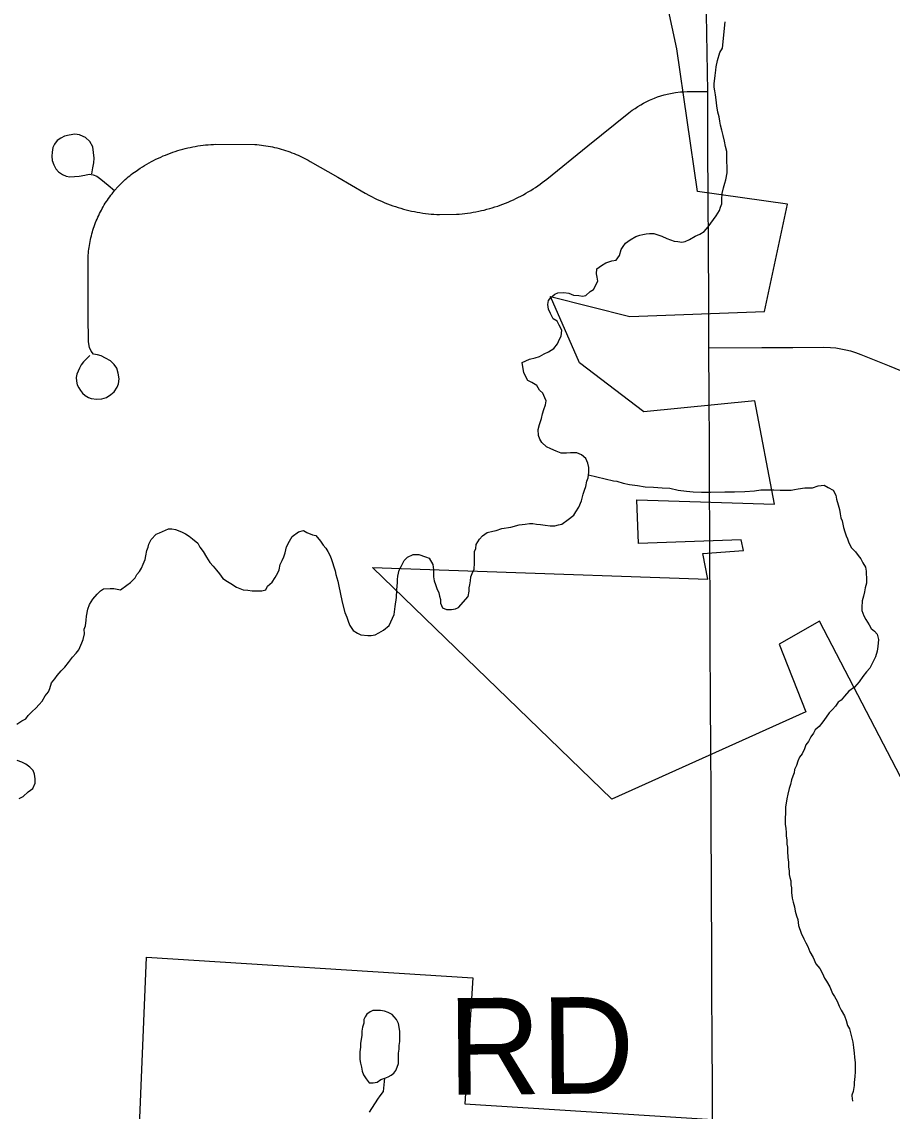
# Model space of a CAD drawing. Extents: x -11.4 to 84.1, y 11.1 to 59.
# Drawn here: x 26.89 to 27.402, y 45.956 to 46.596 of the extents above; entities that cross this region are included whole.
import ezdxf

# ---------------------------------------------------------------- set-up
doc = ezdxf.new("R2010")
doc.units = 0
for name, color, linetype in [('GM_X_Corporation', 7, 'Continuous'), ('GM_X_County_Road', 7, 'Continuous'), ('GM_X_County_Road_Text', 7, 'Continuous'), ('GM_X_Minor_Lake', 7, 'Continuous'), ('GM_X_Minor_River', 7, 'Continuous'), ('GM_X_Township_Road', 7, 'Continuous')]:
    doc.layers.add(name, color=color, linetype=linetype)

msp = doc.modelspace()

# ---------------------------------------------------------------- linework, layer by layer
at = {"layer": 'GM_X_Corporation'}
for points in [[(27.43663, 46.09513), (27.359, 46.2441), (27.33545, 46.23057), (27.35107, 46.19098), (27.23691, 46.13949), (27.09623, 46.27579), (27.15799, 46.27364), (27.29351, 46.26891), (27.29058, 46.28397), (27.31447, 46.28564), (27.31294, 46.29191), (27.25256, 46.2898), (27.25166, 46.31554), (27.33264, 46.31288), (27.32099, 46.37373), (27.25585, 46.36726), (27.21805, 46.39609), (27.20099, 46.43491), (27.24749, 46.42332), (27.3268, 46.42609), (27.34022, 46.48926), (27.28741, 46.49669), (27.27514, 46.58055), (27.2676, 46.61619)], [(26.95209, 45.77262), (26.96335, 46.04662), (27.1552, 46.03447), (27.15053, 45.96055), (27.47941, 45.93974)]]:
    msp.add_lwpolyline(points, dxfattribs=at)
at = {"layer": 'GM_X_County_Road'}
msp.add_lwpolyline([(27.29624, 45.94436), (27.29613, 45.97072), (27.29603, 45.99707), (27.29587, 46.02814), (27.29572, 46.05921), (27.29564, 46.07552), (27.29555, 46.09183), (27.29541, 46.1229), (27.2953, 46.14527), (27.2952, 46.16763), (27.29505, 46.1987), (27.29489, 46.22977), (27.29477, 46.25555), (27.29464, 46.28133), (27.29455, 46.30011), (27.29446, 46.31888), (27.29433, 46.34749), (27.29421, 46.37609), (27.29408, 46.40482), (27.29393, 46.434), (27.29377, 46.46318), (27.29363, 46.49425), (27.29351, 46.52132), (27.29338, 46.5484), (27.29335, 46.55551), (27.293, 46.57827), (27.29265, 46.60103)], dxfattribs=at)
at = {"layer": 'GM_X_Minor_Lake'}
for points in [[(27.09936, 46.0154), (27.09643, 46.01541), (27.09492, 46.01466), (27.09302, 46.01314), (27.09187, 46.01163), (27.09111, 46.01012), (27.0911, 46.00784), (27.09034, 46.00557), (27.08995, 46.00329), (27.08994, 46.00063), (27.08916, 45.99608), (27.08916, 45.99381), (27.08877, 45.99115), (27.08875, 45.9866), (27.08912, 45.98432), (27.08987, 45.98204), (27.09024, 45.97976), (27.09099, 45.97748), (27.0925, 45.9752), (27.09438, 45.97292)], [(27.09438, 45.97292), (27.09666, 45.97291), (27.09893, 45.97328), (27.10121, 45.97479), (27.10349, 45.97554), (27.10538, 45.97629), (27.10728, 45.97743), (27.1088, 45.97856), (27.10994, 45.98007), (27.11071, 45.98197), (27.11147, 45.98424), (27.1115, 45.99031), (27.11188, 45.99259), (27.11189, 45.99487), (27.11228, 45.99714), (27.1123, 46.00321), (27.11156, 46.00777), (27.11043, 46.01005), (27.10892, 46.01157), (27.10779, 46.01309), (27.10552, 46.01424), (27.10325, 46.01501), (27.10098, 46.01539), (27.09936, 46.0154)]]:
    msp.add_lwpolyline(points, dxfattribs=at)
at = {"layer": 'GM_X_Minor_River'}
for points in [[(27.25108, 46.47029), (27.25335, 46.47109), (27.25524, 46.4715), (27.25714, 46.47191), (27.25903, 46.47194), (27.26169, 46.47199), (27.26398, 46.47127), (27.26628, 46.47054), (27.26934, 46.46907), (27.27354, 46.46762), (27.27583, 46.46728), (27.27811, 46.46693), (27.28, 46.46734), (27.28264, 46.46853), (27.28603, 46.47049), (27.28867, 46.47167), (27.2913, 46.47324), (27.29353, 46.47593), (27.29836, 46.48248), (27.30021, 46.48555), (27.30093, 46.48746), (27.30166, 46.48938), (27.30162, 46.49204), (27.30194, 46.49546), (27.30264, 46.4989), (27.30336, 46.50157), (27.30408, 46.50349), (27.30477, 46.50768), (27.30474, 46.50958), (27.30471, 46.51148), (27.30467, 46.51414), (27.30462, 46.5168), (27.30456, 46.52022), (27.30375, 46.52325), (27.30332, 46.52629), (27.3025, 46.5297), (27.30169, 46.53273), (27.30088, 46.53575), (27.30047, 46.53803), (27.30004, 46.54068), (27.29924, 46.54333), (27.29879, 46.54713), (27.29836, 46.55054), (27.29793, 46.55358), (27.29751, 46.55585), (27.29709, 46.55813), (27.29706, 46.56003), (27.29773, 46.56498), (27.29806, 46.56803), (27.29841, 46.56994), (27.29911, 46.57375), (27.30055, 46.57834), (27.30202, 46.58102), (27.30368, 46.59651)], [(27.15911, 46.29234), (27.16098, 46.29427), (27.16361, 46.29622), (27.16701, 46.29703), (27.1689, 46.29744), (27.1723, 46.29864), (27.17761, 46.29949), (27.18252, 46.30071), (27.18593, 46.30115), (27.18859, 46.30157), (27.19048, 46.3016), (27.19277, 46.30126), (27.19505, 46.30092), (27.19772, 46.30058), (27.20076, 46.30025), (27.20342, 46.30029), (27.20569, 46.30071), (27.20758, 46.30112), (27.21134, 46.30385), (27.21471, 46.30656), (27.21582, 46.30848), (27.21767, 46.31118), (27.21913, 46.315), (27.2202, 46.31882), (27.22092, 46.32111), (27.22165, 46.32341), (27.22235, 46.32646), (27.22308, 46.32838), (27.2234, 46.3318), (27.22336, 46.33446), (27.22293, 46.33712), (27.22175, 46.33976), (27.21905, 46.342), (27.21638, 46.34309), (27.21448, 46.34306), (27.21258, 46.34303), (27.2103, 46.34299), (27.20726, 46.34295), (27.20421, 46.34404), (27.20114, 46.34551), (27.19847, 46.3466), (27.19576, 46.34922), (27.19459, 46.3511), (27.19379, 46.35337), (27.19373, 46.35679), (27.19444, 46.35985), (27.19553, 46.36329), (27.19624, 46.36596), (27.19696, 46.36863), (27.19805, 46.37131), (27.19839, 46.3736), (27.1976, 46.37549), (27.19642, 46.37813), (27.19448, 46.38), (27.19292, 46.38264), (27.18985, 46.38449), (27.18755, 46.38559), (27.1852, 46.39011), (27.18434, 46.39618), (27.18848, 46.39815), (27.19189, 46.39897), (27.19453, 46.39977), (27.19717, 46.40134), (27.19981, 46.40252), (27.20281, 46.40447), (27.20504, 46.40717), (27.20614, 46.40985), (27.20725, 46.41177), (27.20757, 46.4152), (27.206, 46.41822), (27.20482, 46.42048), (27.20252, 46.42196), (27.20095, 46.42498), (27.19976, 46.42762), (27.19934, 46.43027), (27.19968, 46.43256), (27.20117, 46.43449), (27.20342, 46.43643), (27.2053, 46.43722), (27.20872, 46.43727), (27.21176, 46.43694), (27.21444, 46.43585), (27.21748, 46.43552), (27.21977, 46.43517), (27.22166, 46.43558), (27.22428, 46.43791), (27.22616, 46.43908), (27.22873, 46.44407), (27.22832, 46.44634), (27.22791, 46.44824), (27.22823, 46.45128), (27.23086, 46.45323), (27.23349, 46.45479), (27.23689, 46.45599), (27.23954, 46.45641), (27.2414, 46.45911), (27.24248, 46.46255), (27.24359, 46.46446), (27.24507, 46.46639), (27.2477, 46.46833), (27.25108, 46.47029)], [(27.22325, 46.33013), (27.23792, 46.32672), (27.23983, 46.32637), (27.24364, 46.32529), (27.24745, 46.32459), (27.25202, 46.32391), (27.25659, 46.32322), (27.26154, 46.32292), (27.26648, 46.32263), (27.27104, 46.32232), (27.276, 46.32126), (27.28095, 46.32058), (27.28475, 46.32026), (27.28969, 46.31996), (27.29501, 46.32005), (27.30336, 46.32019), (27.30906, 46.32028), (27.31513, 46.32038), (27.32082, 46.32086), (27.32462, 46.3213), (27.32841, 46.32136), (27.33221, 46.32142), (27.33601, 46.32111), (27.33981, 46.32117), (27.34247, 46.32121), (27.34436, 46.32163), (27.34663, 46.32204), (27.35043, 46.32249), (27.35232, 46.32252), (27.35498, 46.32256), (27.35838, 46.32376), (27.36179, 46.32419), (27.36409, 46.32271), (27.36716, 46.32124), (27.36873, 46.31822), (27.36915, 46.31595), (27.36996, 46.31254), (27.37077, 46.30989), (27.37119, 46.30724), (27.37161, 46.30496), (27.3724, 46.30307), (27.37322, 46.29928), (27.37403, 46.29664), (27.37483, 46.29437), (27.37562, 46.29248), (27.37642, 46.29021), (27.37798, 46.28719), (27.3803, 46.28495), (27.38186, 46.2827), (27.38341, 46.28082), (27.38459, 46.27856), (27.38615, 46.27592), (27.38657, 46.27365), (27.3866, 46.27174), (27.38663, 46.26984), (27.38669, 46.26642), (27.38597, 46.26375), (27.38563, 46.26146), (27.38492, 46.25879), (27.3842, 46.25611), (27.38389, 46.25231), (27.38392, 46.25041), (27.38511, 46.24738), (27.38629, 46.24512), (27.38824, 46.24211), (27.38941, 46.23985), (27.39134, 46.23836), (27.39289, 46.23649), (27.3937, 46.23345), (27.39339, 46.22927), (27.39305, 46.2266), (27.39197, 46.22316), (27.3905, 46.22009), (27.38866, 46.21664), (27.3868, 46.21433), (27.38457, 46.21163), (27.38234, 46.20855), (27.37974, 46.20547), (27.37636, 46.20313), (27.37375, 46.20004), (27.37189, 46.19773), (27.37001, 46.19656), (27.36853, 46.19426), (27.36666, 46.19232), (27.3648, 46.19039), (27.36294, 46.1877), (27.36109, 46.18501), (27.35886, 46.18231), (27.35661, 46.18037), (27.3555, 46.17845), (27.35402, 46.17615), (27.35254, 46.17346), (27.35106, 46.17153), (27.35034, 46.16924), (27.34887, 46.16617), (27.34738, 46.16425), (27.34628, 46.16195), (27.34557, 46.15927), (27.34447, 46.15698), (27.34412, 46.15507), (27.34339, 46.15315)], [(26.88708, 46.18367), (26.89008, 46.18562), (26.89234, 46.1868), (26.89383, 46.18873), (26.89607, 46.19105), (26.89832, 46.19299), (26.90018, 46.1953), (26.90204, 46.19723), (26.90389, 46.2003), (26.90575, 46.20261), (26.90648, 46.20453), (26.90756, 46.20797), (26.90942, 46.21028), (26.91091, 46.2122), (26.91314, 46.2149), (26.91538, 46.21722), (26.91761, 46.21992), (26.91984, 46.223), (26.92208, 46.22532), (26.92357, 46.22724), (26.9254, 46.23146), (26.92612, 46.23337), (26.92683, 46.2368), (26.92678, 46.23946), (26.92751, 46.24138), (26.92783, 46.24481), (26.92817, 46.24709), (26.92886, 46.25129), (26.92996, 46.25396), (26.9318, 46.25704), (26.93441, 46.26012), (26.93628, 46.26206), (26.93816, 46.26323), (26.94196, 46.26329), (26.94423, 46.26333), (26.94804, 46.26263), (26.9518, 46.26535), (26.95405, 46.26691), (26.95666, 46.26961), (26.95777, 46.27153), (26.95926, 46.27346), (26.96036, 46.27538), (26.96147, 46.27768), (26.96256, 46.28036), (26.9629, 46.28265), (26.96361, 46.2857), (26.96434, 46.28761), (26.96468, 46.28952), (26.96616, 46.29221), (26.96915, 46.2953), (26.97103, 46.29609), (26.97631, 46.29846), (26.97821, 46.29849), (26.98049, 46.29815), (26.98394, 46.29668), (26.98623, 46.29558), (26.98854, 46.2941), (26.99046, 46.29261), (26.99354, 46.28999), (26.99472, 46.28773), (26.99667, 46.2851), (26.99862, 46.28171), (27.00057, 46.2787), (27.00251, 46.27645), (27.00444, 46.2742), (27.00638, 46.27195), (27.00833, 46.26933)], [(27.00833, 46.26933), (27.01102, 46.26747), (27.01293, 46.26636), (27.01639, 46.26413), (27.0183, 46.2634), (27.02021, 46.26268), (27.02288, 46.26234), (27.02554, 46.262), (27.02896, 46.26206), (27.03124, 46.2621), (27.03351, 46.26251), (27.03461, 46.26481), (27.03723, 46.26714), (27.03908, 46.26983), (27.04056, 46.27252), (27.04129, 46.27443), (27.04199, 46.27749), (27.0431, 46.27978), (27.0442, 46.28208), (27.04492, 46.28438), (27.04562, 46.28781), (27.04746, 46.29126), (27.04893, 46.29395), (27.05269, 46.29667), (27.05571, 46.29748), (27.05763, 46.29637), (27.06107, 46.29491), (27.06298, 46.29456), (27.06569, 46.29118), (27.06725, 46.28893), (27.0688, 46.28705), (27.06997, 46.28517), (27.07115, 46.28291), (27.07194, 46.28102), (27.07274, 46.27875), (27.07354, 46.2761), (27.07434, 46.27383), (27.07476, 46.27156), (27.07596, 46.26777), (27.07639, 46.26474), (27.07722, 46.26095), (27.07845, 46.25527), (27.08007, 46.24921), (27.08126, 46.24657), (27.08207, 46.24354), (27.08286, 46.24165), (27.08481, 46.23864), (27.08749, 46.23716), (27.08941, 46.23606), (27.09359, 46.23574), (27.09549, 46.23577), (27.09776, 46.23619), (27.10002, 46.23737), (27.10265, 46.23893), (27.10603, 46.24165), (27.10896, 46.24817), (27.10964, 46.25274), (27.11031, 46.25807), (27.11061, 46.26264), (27.11092, 46.26683), (27.11089, 46.26873), (27.11124, 46.27064), (27.11194, 46.27407), (27.11304, 46.27637), (27.11488, 46.27982), (27.11675, 46.28176), (27.12014, 46.28333), (27.12356, 46.28339), (27.12738, 46.28193), (27.12967, 46.28121), (27.13164, 46.27744), (27.13207, 46.2744), (27.1321, 46.2725), (27.13214, 46.27022), (27.13256, 46.26795), (27.13335, 46.26568), (27.13415, 46.26341), (27.13533, 46.26077), (27.13575, 46.25887), (27.13616, 46.25698), (27.13619, 46.2547), (27.13738, 46.25206), (27.13968, 46.25095), (27.14272, 46.251), (27.14499, 46.25142), (27.14687, 46.25221), (27.15246, 46.25877), (27.15317, 46.26182), (27.15314, 46.26372), (27.15348, 46.26563), (27.15383, 46.26792), (27.15417, 46.2702), (27.1549, 46.27212), (27.15599, 46.2748), (27.15631, 46.27822), (27.15627, 46.28088), (27.15623, 46.28317), (27.1562, 46.28507), (27.15693, 46.28698), (27.15726, 46.28927), (27.15911, 46.29234)], [(26.88857, 46.13997), (26.89083, 46.14115), (26.89382, 46.14386), (26.89645, 46.1458), (26.89792, 46.14887), (26.89787, 46.15153), (26.89745, 46.15418), (26.89665, 46.15645), (26.89472, 46.15832), (26.89241, 46.16019), (26.89011, 46.16129), (26.88743, 46.16238)], [(27.34339, 46.15315), (27.34267, 46.15086), (27.34195, 46.14819), (27.34123, 46.14589), (27.34053, 46.14246), (27.33982, 46.13979), (27.33914, 46.13483), (27.33893, 46.12494), (27.33935, 46.12229), (27.33939, 46.12001), (27.33942, 46.1181), (27.33985, 46.11545), (27.33988, 46.11317), (27.34029, 46.11127), (27.34033, 46.10899), (27.3404, 46.10519), (27.34082, 46.10254), (27.34087, 46.09988), (27.34129, 46.09722), (27.34132, 46.09532), (27.34173, 46.09343), (27.34215, 46.09153), (27.34218, 46.08925), (27.3426, 46.08736), (27.34264, 46.0847), (27.34308, 46.08128), (27.3435, 46.07901), (27.3443, 46.07636), (27.34472, 46.0737), (27.34553, 46.07106), (27.34633, 46.06879), (27.34676, 46.06537), (27.34836, 46.06083), (27.34993, 46.05744), (27.35111, 46.05517), (27.35229, 46.05291), (27.35348, 46.04989), (27.35544, 46.0465), (27.35702, 46.04272), (27.35934, 46.0401), (27.36091, 46.03709), (27.3621, 46.03444), (27.36327, 46.03256), (27.36522, 46.02917), (27.36601, 46.02728), (27.3668, 46.02539), (27.36798, 46.02351), (27.36954, 46.02088), (27.37073, 46.01785), (27.37191, 46.01559), (27.37386, 46.0122), (27.37467, 46.00955), (27.37548, 46.00652), (27.37665, 46.00464), (27.37868, 45.99669), (27.37911, 45.99366), (27.37955, 45.99024), (27.37959, 45.98796), (27.38003, 45.98454), (27.38008, 45.9815), (27.38011, 45.97922), (27.37978, 45.97655), (27.37946, 45.97313), (27.37949, 45.97123), (27.37879, 45.96779), (27.37807, 45.9655), (27.37807, 45.96512), (27.3785, 45.96208)], [(27.0945, 45.95551), (27.09931, 45.96319), (27.10079, 45.96512), (27.10265, 45.96781), (27.10347, 45.97554)]]:
    msp.add_lwpolyline(points, dxfattribs=at)
at = {"layer": 'GM_X_Township_Road'}
for points in [[(26.93005, 46.40039), (26.92629, 46.39654), (26.92488, 46.3948), (26.92389, 46.39284), (26.92323, 46.39118), (26.92246, 46.38933), (26.92209, 46.38734), (26.92222, 46.38531), (26.92269, 46.38318), (26.92366, 46.38128), (26.92459, 46.37966), (26.92574, 46.37814), (26.92731, 46.37675), (26.92921, 46.37573), (26.93088, 46.37507), (26.93425, 46.37472), (26.93703, 46.37481), (26.93985, 46.37564), (26.94234, 46.37735), (26.94433, 46.37897), (26.94618, 46.38175), (26.94691, 46.3837), (26.94723, 46.38667), (26.94674, 46.38995), (26.94584, 46.39283), (26.94428, 46.39497), (26.94214, 46.39719), (26.93918, 46.39883), (26.93663, 46.40014), (26.93458, 46.40064), (26.9322, 46.40106), (26.93079, 46.40289), (26.9299, 46.405), (26.92926, 46.40827), (26.92908, 46.42391), (26.929, 46.43945), (26.92913, 46.45927), (26.92923, 46.46044), (26.92933, 46.46159), (26.92947, 46.46273), (26.92961, 46.46388), (26.92981, 46.46502), (26.92999, 46.46617), (26.93018, 46.4673), (26.93042, 46.46843), (26.93071, 46.46956), (26.93099, 46.47069), (26.93127, 46.4718), (26.93156, 46.47292), (26.93189, 46.47403), (26.93227, 46.47513), (26.93265, 46.47623), (26.93303, 46.47733), (26.93341, 46.4784), (26.93384, 46.47948), (26.93431, 46.48054), (26.93478, 46.48161), (26.93526, 46.48266), (26.93573, 46.48371), (26.93626, 46.48474), (26.93683, 46.48577), (26.93735, 46.48678), (26.93796, 46.48778), (26.93853, 46.48878), (26.93914, 46.48976), (26.93977, 46.49074), (26.94042, 46.4917), (26.94109, 46.49265), (26.94175, 46.49359), (26.94242, 46.49452), (26.94313, 46.49544), (26.9446, 46.49723), (26.94678, 46.49967), (26.94758, 46.50051), (26.94839, 46.50133), (26.9492, 46.50214), (26.95005, 46.50295), (26.9509, 46.50373), (26.95176, 46.50449), (26.95266, 46.50524), (26.95356, 46.50598), (26.95446, 46.5067), (26.95536, 46.5074), (26.95631, 46.5081), (26.95726, 46.50876), (26.95967, 46.51042), (26.961, 46.51123), (26.96228, 46.51204), (26.96361, 46.51281), (26.96493, 46.51356), (26.96626, 46.51429), (26.96758, 46.515), (26.96896, 46.51568), (26.97034, 46.51633), (26.97175, 46.51697), (26.97313, 46.51758), (26.97455, 46.51816), (26.97597, 46.51873), (26.9774, 46.51926), (26.97882, 46.51976), (26.98029, 46.52025), (26.98171, 46.52072), (26.98318, 46.52115), (26.98465, 46.52155), (26.98611, 46.52195), (26.98763, 46.5223), (26.9891, 46.52263), (26.99062, 46.52293), (26.99209, 46.52321), (26.9936, 46.52347), (26.99512, 46.52369), (26.99663, 46.52389), (26.99815, 46.52406), (26.99967, 46.52421), (27.00118, 46.52433), (27.0027, 46.52443), (27.00421, 46.52449), (27.02701, 46.52438), (27.02833, 46.52427), (27.02966, 46.52415), (27.03098, 46.524), (27.03226, 46.52383), (27.03359, 46.52363), (27.03487, 46.52341), (27.0362, 46.52318), (27.03748, 46.5229), (27.03873, 46.52262), (27.04008, 46.52231), (27.04136, 46.52199), (27.04264, 46.52164), (27.04387, 46.52126), (27.04515, 46.52086), (27.04638, 46.52044), (27.04766, 46.51999), (27.04889, 46.51953), (27.05012, 46.51905), (27.05136, 46.51855), (27.05254, 46.51802), (27.05377, 46.51747), (27.05496, 46.5169), (27.05614, 46.51631), (27.05732, 46.51571), (27.05846, 46.51507), (27.05965, 46.51441), (27.0758, 46.50509), (27.09195, 46.49578), (27.09456, 46.49433), (27.09602, 46.49356), (27.09749, 46.49283), (27.09896, 46.4921), (27.10048, 46.49142), (27.10199, 46.49075), (27.10351, 46.49011), (27.10507, 46.4895), (27.10659, 46.48891), (27.10815, 46.48835), (27.10971, 46.48783), (27.11133, 46.48732), (27.11289, 46.48685), (27.1145, 46.48641), (27.11606, 46.48598), (27.11767, 46.4856), (27.11928, 46.48524), (27.12094, 46.48491), (27.12255, 46.4846), (27.12416, 46.48432), (27.12582, 46.48407), (27.12743, 46.48384), (27.12909, 46.48366), (27.13075, 46.48349), (27.1324, 46.48336), (27.13402, 46.48325), (27.13568, 46.48317), (27.14563, 46.48332), (27.14724, 46.48343), (27.14889, 46.48359), (27.15055, 46.48378), (27.15216, 46.48399), (27.15382, 46.48423), (27.15543, 46.4845), (27.15709, 46.48479), (27.1587, 46.48511), (27.16032, 46.48547), (27.16192, 46.48584), (27.16353, 46.48626), (27.16515, 46.4867), (27.16671, 46.48716), (27.16827, 46.48765), (27.16988, 46.48817), (27.1714, 46.48872), (27.17297, 46.4893), (27.17453, 46.4899), (27.17605, 46.49053), (27.17756, 46.49118), (27.17908, 46.49187), (27.18055, 46.49257), (27.18206, 46.4933), (27.18354, 46.49406), (27.18495, 46.49485), (27.18643, 46.49566), (27.18785, 46.49649), (27.18926, 46.49735), (27.19064, 46.49823), (27.19202, 46.49915), (27.19339, 46.50008), (27.19476, 46.50104), (27.19609, 46.50201), (27.19742, 46.50302), (27.1987, 46.50404), (27.22282, 46.52347), (27.24695, 46.5429), (27.24898, 46.54444), (27.2506, 46.54559), (27.25226, 46.54668), (27.25396, 46.54771), (27.25567, 46.54868), (27.25922, 46.55043), (27.26107, 46.55121), (27.26197, 46.55159), (27.26387, 46.55227), (27.26571, 46.55289), (27.26766, 46.55344), (27.27055, 46.55415), (27.27249, 46.55454), (27.27444, 46.55486), (27.27737, 46.55521), (27.27936, 46.55536), (27.28135, 46.55544), (27.29335, 46.55551)], [(26.9313, 46.50707), (26.93189, 46.51067), (26.93244, 46.51355), (26.93266, 46.51633), (26.93189, 46.52298), (26.92999, 46.52605), (26.9275, 46.52838), (26.92615, 46.52909), (26.92396, 46.53004), (26.92116, 46.53037), (26.91788, 46.52988), (26.91524, 46.5293), (26.91303, 46.52809), (26.91084, 46.52663), (26.90923, 46.52458), (26.90834, 46.52248), (26.90801, 46.51977), (26.90777, 46.51757), (26.90795, 46.51495), (26.9088, 46.51245), (26.91011, 46.50997), (26.91162, 46.50818), (26.91401, 46.5067), (26.91607, 46.5058), (26.91837, 46.50539), (26.92385, 46.50573), (26.92713, 46.50639), (26.92966, 46.50688), (26.93198, 46.50643), (26.93423, 46.50572), (26.9366, 46.50399), (26.94081, 46.50043), (26.9446, 46.49723)], [(27.29408, 46.40482), (27.32515, 46.40497), (27.34342, 46.40507), (27.36169, 46.40515), (27.36562, 46.40503), (27.3686, 46.40476), (27.37154, 46.40433), (27.37448, 46.40375), (27.37737, 46.40302), (27.38021, 46.40213), (27.38329, 46.40098), (27.39996, 46.39423), (27.41664, 46.38748)]]:
    msp.add_lwpolyline(points, dxfattribs=at)

# ---------------------------------------------------------------- texts
at = {"layer": 'GM_X_County_Road_Text'}
msp.add_text('RD', height=0.056818, rotation=0.49731, dxfattribs=at).set_placement((27.14068, 45.96575))

doc.saveas('drawing.dxf')
